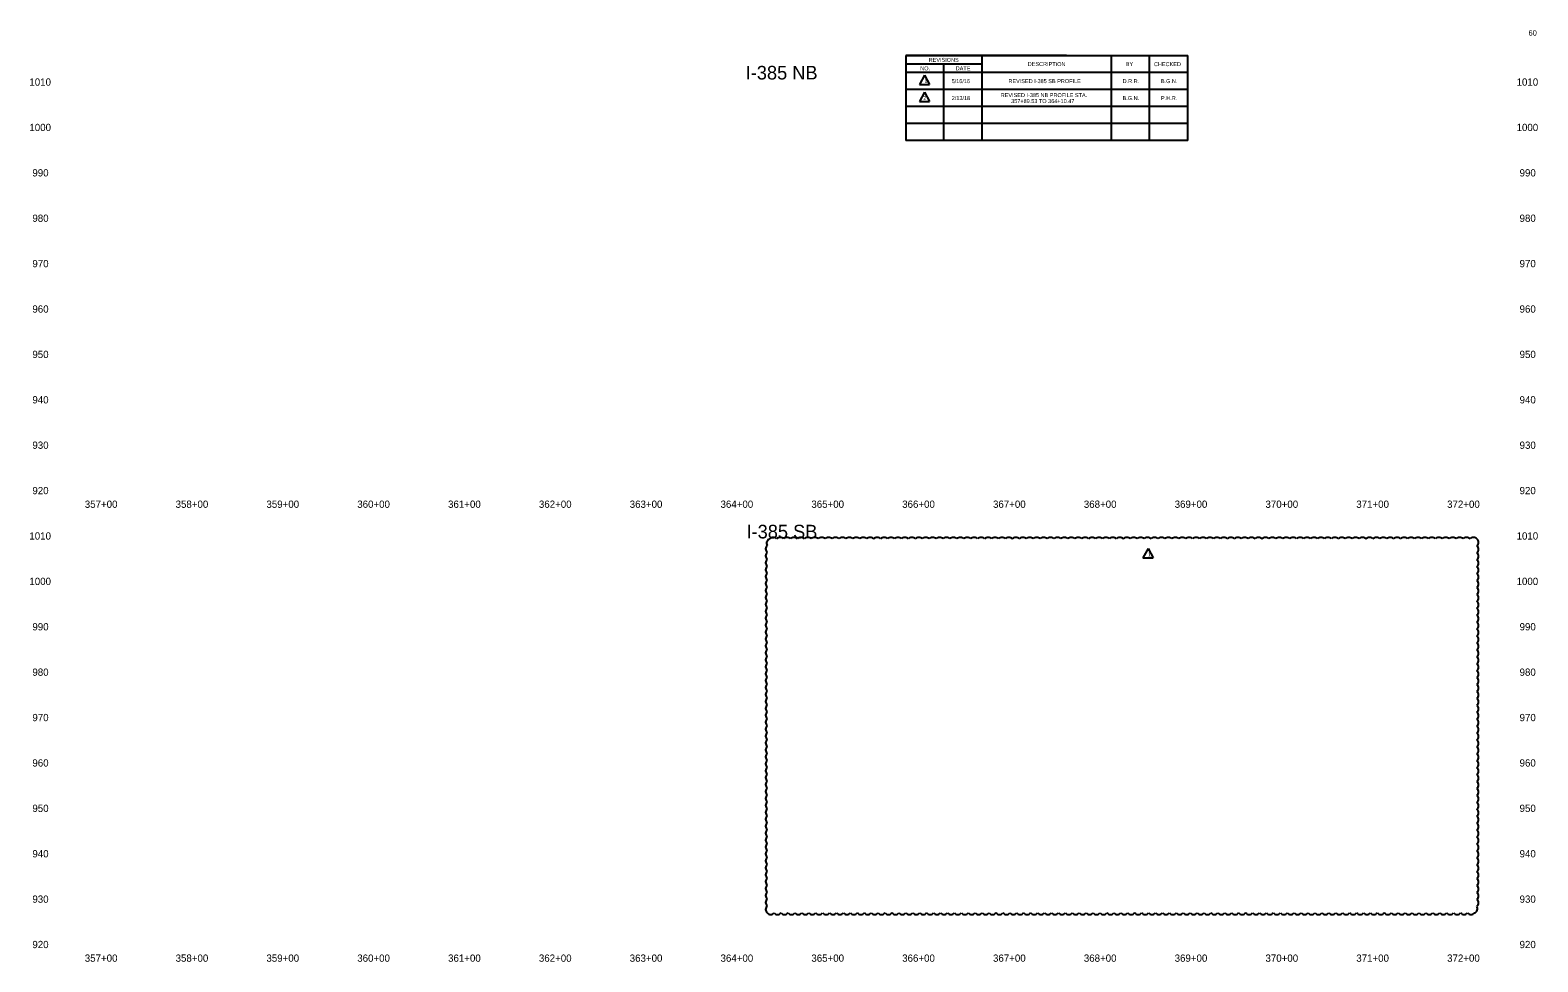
# Model space of a CAD drawing. Extents: x 1616157 to 1617818, y 1076017 to 1077043.
import ezdxf

# ---------------------------------------------------------------- set-up
doc = ezdxf.new("R2010")
doc.units = 0
doc.layers.add('Default', color=7, linetype='Continuous')
doc.layers.add('RD_SHT_TX', color=7, linetype='Continuous')

msp = doc.modelspace()

# ---------------------------------------------------------------- linework, layer by layer
at = {"layer": 'RD_SHT_TX'}
for p, q in [((1617121.5, 1077015.4), (1617432.1, 1077015.4)), ((1617298.7, 1077015.4), (1617121.5, 1077015.4)), ((1617121.5, 1077015.4), (1617121.5, 1076921.9)), ((1617205.5, 1077006.1), (1617121.5, 1077006.1)), ((1617163.5, 1076921.9), (1617163.5, 1077006.1)), ((1617205.5, 1076921.9), (1617205.5, 1077015.4)), ((1617348.1, 1076921.9), (1617348.1, 1077015.4)), ((1617390.1, 1076921.9), (1617390.1, 1077015.4)), ((1617432.1, 1076921.9), (1617432.1, 1077015.4)), ((1617432.1, 1076996.7), (1617121.5, 1076996.7)), ((1617142.1, 1076993.8), (1617136.5, 1076983.6)), ((1617142.1, 1076993.8), (1617147.8, 1076983.6)), ((1617432.1, 1076978), (1617121.5, 1076978)), ((1617136.5, 1076983.6), (1617147.8, 1076983.6)), ((1617142.1, 1076975.1), (1617136.5, 1076964.9)), ((1617142.1, 1076975.1), (1617147.8, 1076964.9)), ((1617432.1, 1076959.3), (1617121.5, 1076959.3)), ((1617136.5, 1076964.9), (1617147.8, 1076964.9)), ((1617432.1, 1076940.6), (1617121.5, 1076940.6)), ((1617432.1, 1076921.9), (1617121.5, 1076921.9)), ((1617388.3, 1076472.4), (1617382.6, 1076462.3)), ((1617388.3, 1076472.4), (1617394, 1076462.3)), ((1617382.6, 1076462.3), (1617394, 1076462.3))]:
    msp.add_line(p, q, dxfattribs=at)
for centre, start, end in [((1616972.2, 1076472.1), 130, 230), ((1616973.3, 1076478.3), 108.9596, 208.9596), ((1616975.5, 1076479.8), 40, 140), ((1616983.2, 1076479.8), 40, 140), ((1616990.8, 1076479.8), 40, 140), ((1616998.4, 1076479.8), 40, 140), ((1617006.1, 1076479.8), 40, 140), ((1617013.7, 1076479.8), 40, 140), ((1617021.3, 1076479.8), 40, 140), ((1617029, 1076479.8), 40, 140), ((1617036.6, 1076479.8), 40, 140), ((1617044.2, 1076479.8), 40, 140), ((1617051.9, 1076479.8), 40, 140), ((1617059.5, 1076479.8), 40, 140), ((1617067.1, 1076479.8), 40, 140), ((1617074.8, 1076479.8), 40, 140), ((1617082.4, 1076479.8), 40, 140), ((1617090, 1076479.8), 40, 140), ((1617097.7, 1076479.8), 40, 140), ((1617105.3, 1076479.8), 40, 140), ((1617113, 1076479.8), 40, 140), ((1617120.6, 1076479.8), 40, 140), ((1617128.2, 1076479.8), 40, 140), ((1617135.9, 1076479.8), 40, 140), ((1617143.5, 1076479.8), 40, 140), ((1617151.1, 1076479.8), 40, 140), ((1617158.8, 1076479.8), 40, 140), ((1617166.4, 1076479.8), 40, 140), ((1617174, 1076479.8), 40, 140), ((1617181.7, 1076479.8), 40, 140), ((1617189.3, 1076479.8), 40, 140), ((1617196.9, 1076479.8), 40, 140), ((1617204.6, 1076479.8), 40, 140), ((1617212.2, 1076479.8), 40, 140), ((1617219.8, 1076479.8), 40, 140), ((1617227.5, 1076479.8), 40, 140), ((1617235.1, 1076479.8), 40, 140), ((1617242.7, 1076479.8), 40, 140), ((1617250.4, 1076479.8), 40, 140), ((1617258, 1076479.8), 40, 140), ((1617265.7, 1076479.8), 40, 140), ((1617273.3, 1076479.8), 40, 140), ((1617280.9, 1076479.8), 40, 140), ((1617288.6, 1076479.8), 40, 140), ((1617296.2, 1076479.8), 40, 140), ((1617303.8, 1076479.8), 40, 140), ((1617311.5, 1076479.8), 40, 140), ((1617319.1, 1076479.8), 40, 140), ((1617326.7, 1076479.8), 40, 140), ((1617334.4, 1076479.8), 40, 140), ((1617342, 1076479.8), 40, 140), ((1617349.6, 1076479.8), 40, 140), ((1617357.3, 1076479.8), 40, 140), ((1617364.9, 1076479.8), 40, 140), ((1617372.5, 1076479.8), 40, 140), ((1617380.2, 1076479.8), 40, 140), ((1617387.8, 1076479.8), 40, 140), ((1617395.4, 1076479.8), 40, 140), ((1617403.1, 1076479.8), 40, 140), ((1617410.7, 1076479.8), 40, 140), ((1617418.4, 1076479.8), 40, 140), ((1617426, 1076479.8), 40, 140), ((1617433.6, 1076479.8), 40, 140), ((1617441.3, 1076479.8), 40, 140), ((1617448.9, 1076479.8), 40, 140), ((1617456.5, 1076479.8), 40, 140), ((1617464.2, 1076479.8), 40, 140), ((1617471.8, 1076479.8), 40, 140), ((1617479.4, 1076479.8), 40, 140), ((1617487.1, 1076479.8), 40, 140), ((1617494.7, 1076479.8), 40, 140), ((1617502.3, 1076479.8), 40, 140), ((1617510, 1076479.8), 40, 140), ((1617517.6, 1076479.8), 40, 140), ((1617525.2, 1076479.8), 40, 140), ((1617532.9, 1076479.8), 40, 140), ((1617540.5, 1076479.8), 40, 140), ((1617548.1, 1076479.8), 40, 140), ((1617555.8, 1076479.8), 40, 140), ((1617563.4, 1076479.8), 40, 140), ((1617571.1, 1076479.8), 40, 140), ((1617578.7, 1076479.8), 40, 140), ((1617586.3, 1076479.8), 40, 140), ((1617594, 1076479.8), 40, 140), ((1617601.6, 1076479.8), 40, 140), ((1617609.2, 1076479.8), 40, 140), ((1617616.9, 1076479.8), 40, 140), ((1617624.5, 1076479.8), 40, 140), ((1617632.1, 1076479.8), 40, 140), ((1617639.8, 1076479.8), 40, 140), ((1617647.4, 1076479.8), 40, 140), ((1617655, 1076479.8), 40, 140), ((1617662.7, 1076479.8), 40, 140), ((1617670.3, 1076479.8), 40, 140), ((1617677.9, 1076479.8), 40, 140), ((1617685.6, 1076479.8), 40, 140), ((1617693.2, 1076479.8), 40, 140), ((1617700.8, 1076479.8), 40, 140), ((1617708.5, 1076479.8), 40, 140), ((1617716.1, 1076479.8), 40, 140), ((1617723.8, 1076479.8), 40, 140), ((1617731.4, 1076479.8), 40, 140), ((1617739, 1076479.8), 40, 140), ((1617746.7, 1076479.8), 40, 140), ((1617747.3, 1076479.2), 310, 50), ((1617747.3, 1076471.5), 310, 50), ((1616972.2, 1076464.4), 130, 230), ((1616972.2, 1076456.8), 130, 230), ((1617747.3, 1076463.9), 310, 50), ((1617747.3, 1076456.3), 310, 50), ((1616972.2, 1076449.1), 130, 230), ((1616972.2, 1076441.5), 130, 230), ((1616972.2, 1076433.9), 130, 230), ((1617747.3, 1076448.6), 310, 50), ((1617747.3, 1076441), 310, 50), ((1617747.3, 1076433.4), 310, 50), ((1616972.2, 1076426.2), 130, 230), ((1616972.2, 1076418.6), 130, 230), ((1617747.3, 1076425.7), 310, 50), ((1617747.3, 1076418.1), 310, 50), ((1616972.2, 1076411), 130, 230), ((1616972.2, 1076403.3), 130, 230), ((1617747.3, 1076410.5), 310, 50), ((1617747.3, 1076402.8), 310, 50), ((1616972.2, 1076395.7), 130, 230), ((1616972.2, 1076388.1), 130, 230), ((1617747.3, 1076395.2), 310, 50), ((1617747.3, 1076387.6), 310, 50), ((1616972.2, 1076380.4), 130, 230), ((1616972.2, 1076372.8), 130, 230), ((1617747.3, 1076379.9), 310, 50), ((1617747.3, 1076372.3), 310, 50), ((1616972.2, 1076365.2), 130, 230), ((1616972.2, 1076357.5), 130, 230), ((1617747.3, 1076364.7), 310, 50), ((1617747.3, 1076357), 310, 50), ((1616972.2, 1076349.9), 130, 230), ((1616972.2, 1076342.3), 130, 230), ((1616972.2, 1076334.6), 130, 230), ((1617747.3, 1076349.4), 310, 50), ((1617747.3, 1076341.7), 310, 50), ((1617747.3, 1076334.1), 310, 50), ((1616972.2, 1076327), 130, 230), ((1616972.2, 1076319.4), 130, 230), ((1617747.3, 1076326.5), 310, 50), ((1617747.3, 1076318.8), 310, 50), ((1616972.2, 1076311.7), 130, 230), ((1616972.2, 1076304.1), 130, 230), ((1617747.3, 1076311.2), 310, 50), ((1617747.3, 1076303.6), 310, 50), ((1616972.2, 1076296.4), 130, 230), ((1616972.2, 1076288.8), 130, 230), ((1617747.3, 1076295.9), 310, 50), ((1617747.3, 1076288.3), 310, 50), ((1616972.2, 1076281.2), 130, 230), ((1616972.2, 1076273.5), 130, 230), ((1617747.3, 1076280.7), 310, 50), ((1617747.3, 1076273), 310, 50), ((1616972.2, 1076265.9), 130, 230), ((1616972.2, 1076258.3), 130, 230), ((1616972.2, 1076250.6), 130, 230), ((1617747.3, 1076265.4), 310, 50), ((1617747.3, 1076257.8), 310, 50), ((1616972.2, 1076243), 130, 230), ((1616972.2, 1076235.4), 130, 230), ((1617747.3, 1076250.1), 310, 50), ((1617747.3, 1076242.5), 310, 50), ((1617747.3, 1076234.9), 310, 50), ((1616972.2, 1076227.7), 130, 230), ((1616972.2, 1076220.1), 130, 230), ((1617747.3, 1076227.2), 310, 50), ((1617747.3, 1076219.6), 310, 50), ((1616972.2, 1076212.5), 130, 230), ((1616972.2, 1076204.8), 130, 230), ((1617747.3, 1076212), 310, 50), ((1617747.3, 1076204.3), 310, 50), ((1616972.2, 1076197.2), 130, 230), ((1616972.2, 1076189.6), 130, 230), ((1617747.3, 1076196.7), 310, 50), ((1617747.3, 1076189), 310, 50), ((1616972.2, 1076181.9), 130, 230), ((1616972.2, 1076174.3), 130, 230), ((1617747.3, 1076181.4), 310, 50), ((1617747.3, 1076173.8), 310, 50), ((1616972.2, 1076166.7), 130, 230), ((1616972.2, 1076159), 130, 230), ((1616972.2, 1076151.4), 130, 230), ((1617747.3, 1076166.1), 310, 50), ((1617747.3, 1076158.5), 310, 50), ((1617747.3, 1076150.9), 310, 50), ((1616972.2, 1076143.7), 130, 230), ((1616972.2, 1076136.1), 130, 230), ((1617747.3, 1076143.2), 310, 50), ((1617747.3, 1076135.6), 310, 50), ((1616972.2, 1076128.5), 130, 230), ((1616972.2, 1076120.8), 130, 230), ((1617747.3, 1076128), 310, 50), ((1617747.3, 1076120.3), 310, 50), ((1616972.2, 1076113.2), 130, 230), ((1616972.2, 1076105.6), 130, 230), ((1617747.3, 1076112.7), 310, 50), ((1617747.3, 1076105.1), 310, 50), ((1616972.2, 1076097.9), 130, 230), ((1616972.2, 1076090.3), 130, 230), ((1617747.3, 1076097.4), 310, 50), ((1617747.3, 1076089.8), 310, 50), ((1616972.2, 1076082.7), 130, 230), ((1616972.2, 1076075), 130, 230), ((1617746.1, 1076075.9), 288.9596, 28.9596), ((1617747.3, 1076082.2), 310, 50), ((1616972.8, 1076074.4), 220, 320), ((1616980.4, 1076074.4), 220, 320), ((1616988.1, 1076074.4), 220, 320), ((1616995.7, 1076074.4), 220, 320), ((1617003.3, 1076074.4), 220, 320), ((1617011, 1076074.4), 220, 320), ((1617018.6, 1076074.4), 220, 320), ((1617026.2, 1076074.4), 220, 320), ((1617033.9, 1076074.4), 220, 320), ((1617041.5, 1076074.4), 220, 320), ((1617049.1, 1076074.4), 220, 320), ((1617056.8, 1076074.4), 220, 320), ((1617064.4, 1076074.4), 220, 320), ((1617072, 1076074.4), 220, 320), ((1617079.7, 1076074.4), 220, 320), ((1617087.3, 1076074.4), 220, 320), ((1617094.9, 1076074.4), 220, 320), ((1617102.6, 1076074.4), 220, 320), ((1617110.2, 1076074.4), 220, 320), ((1617117.8, 1076074.4), 220, 320), ((1617125.5, 1076074.4), 220, 320), ((1617133.1, 1076074.4), 220, 320), ((1617140.8, 1076074.4), 220, 320), ((1617148.4, 1076074.4), 220, 320), ((1617156, 1076074.4), 220, 320), ((1617163.7, 1076074.4), 220, 320), ((1617171.3, 1076074.4), 220, 320), ((1617178.9, 1076074.4), 220, 320), ((1617186.6, 1076074.4), 220, 320), ((1617194.2, 1076074.4), 220, 320), ((1617201.8, 1076074.4), 220, 320), ((1617209.5, 1076074.4), 220, 320), ((1617217.1, 1076074.4), 220, 320), ((1617224.7, 1076074.4), 220, 320), ((1617232.4, 1076074.4), 220, 320), ((1617240, 1076074.4), 220, 320), ((1617247.6, 1076074.4), 220, 320), ((1617255.3, 1076074.4), 220, 320), ((1617262.9, 1076074.4), 220, 320), ((1617270.5, 1076074.4), 220, 320), ((1617278.2, 1076074.4), 220, 320), ((1617285.8, 1076074.4), 220, 320), ((1617293.5, 1076074.4), 220, 320), ((1617301.1, 1076074.4), 220, 320), ((1617308.7, 1076074.4), 220, 320), ((1617316.4, 1076074.4), 220, 320), ((1617324, 1076074.4), 220, 320), ((1617331.6, 1076074.4), 220, 320), ((1617339.3, 1076074.4), 220, 320), ((1617346.9, 1076074.4), 220, 320), ((1617354.5, 1076074.4), 220, 320), ((1617362.2, 1076074.4), 220, 320), ((1617369.8, 1076074.4), 220, 320), ((1617377.4, 1076074.4), 220, 320), ((1617385.1, 1076074.4), 220, 320), ((1617392.7, 1076074.4), 220, 320), ((1617400.3, 1076074.4), 220, 320), ((1617408, 1076074.4), 220, 320), ((1617415.6, 1076074.4), 220, 320), ((1617423.2, 1076074.4), 220, 320), ((1617430.9, 1076074.4), 220, 320), ((1617438.5, 1076074.4), 220, 320), ((1617446.2, 1076074.4), 220, 320), ((1617453.8, 1076074.4), 220, 320), ((1617461.4, 1076074.4), 220, 320), ((1617469.1, 1076074.4), 220, 320), ((1617476.7, 1076074.4), 220, 320), ((1617484.3, 1076074.4), 220, 320), ((1617492, 1076074.4), 220, 320), ((1617499.6, 1076074.4), 220, 320), ((1617507.2, 1076074.4), 220, 320), ((1617514.9, 1076074.4), 220, 320), ((1617522.5, 1076074.4), 220, 320), ((1617530.1, 1076074.4), 220, 320), ((1617537.8, 1076074.4), 220, 320), ((1617545.4, 1076074.4), 220, 320), ((1617553, 1076074.4), 220, 320), ((1617560.7, 1076074.4), 220, 320), ((1617568.3, 1076074.4), 220, 320), ((1617576, 1076074.4), 220, 320), ((1617583.6, 1076074.4), 220, 320), ((1617591.2, 1076074.4), 220, 320), ((1617598.9, 1076074.4), 220, 320), ((1617606.5, 1076074.4), 220, 320), ((1617614.1, 1076074.4), 220, 320), ((1617621.8, 1076074.4), 220, 320), ((1617629.4, 1076074.4), 220, 320), ((1617637, 1076074.4), 220, 320), ((1617644.7, 1076074.4), 220, 320), ((1617652.3, 1076074.4), 220, 320), ((1617659.9, 1076074.4), 220, 320), ((1617667.6, 1076074.4), 220, 320), ((1617675.2, 1076074.4), 220, 320), ((1617682.8, 1076074.4), 220, 320), ((1617690.5, 1076074.4), 220, 320), ((1617698.1, 1076074.4), 220, 320), ((1617705.7, 1076074.4), 220, 320), ((1617713.4, 1076074.4), 220, 320), ((1617721, 1076074.4), 220, 320), ((1617728.7, 1076074.4), 220, 320), ((1617736.3, 1076074.4), 220, 320), ((1617743.9, 1076074.4), 220, 320)]:
    msp.add_arc(centre, 4.98, start, end, dxfattribs=at)

# ---------------------------------------------------------------- texts
at = {"layer": 'Default'}
for s, p in [('1010', (1616156.6, 1076982.3)), ('1010', (1617794.1, 1076982.3)), ('1000', (1616156.6, 1076932.3)), ('1000', (1617794.1, 1076932.3)), ('990', (1616159.9, 1076882.3)), ('990', (1617797.4, 1076882.3)), ('980', (1616159.9, 1076832.3)), ('980', (1617797.4, 1076832.3)), ('970', (1616159.9, 1076782.3)), ('970', (1617797.4, 1076782.3)), ('960', (1616159.9, 1076732.3)), ('960', (1617797.4, 1076732.3)), ('950', (1616159.9, 1076682.3)), ('950', (1617797.4, 1076682.3)), ('940', (1616159.9, 1076632.3)), ('940', (1617797.4, 1076632.3)), ('930', (1616159.9, 1076582.3)), ('930', (1617797.4, 1076582.3)), ('920', (1616159.9, 1076532.3)), ('920', (1617797.4, 1076532.3)), ('357+00', (1616217.6, 1076517.3)), ('358+00', (1616317.6, 1076517.3)), ('359+00', (1616417.6, 1076517.3)), ('360+00', (1616517.6, 1076517.3)), ('361+00', (1616617.6, 1076517.3)), ('362+00', (1616717.6, 1076517.3)), ('363+00', (1616817.6, 1076517.3)), ('364+00', (1616917.6, 1076517.3)), ('365+00', (1617017.6, 1076517.3)), ('366+00', (1617117.6, 1076517.3)), ('367+00', (1617217.6, 1076517.3)), ('368+00', (1617317.6, 1076517.3)), ('369+00', (1617417.6, 1076517.3)), ('370+00', (1617517.6, 1076517.3)), ('371+00', (1617617.6, 1076517.3)), ('372+00', (1617717.6, 1076517.3)), ('1010', (1616156.6, 1076482.3)), ('1010', (1617794.1, 1076482.3)), ('1000', (1616156.6, 1076432.3)), ('1000', (1617794.1, 1076432.3)), ('990', (1616159.9, 1076382.3)), ('990', (1617797.4, 1076382.3)), ('980', (1616159.9, 1076332.3)), ('980', (1617797.4, 1076332.3)), ('970', (1616159.9, 1076282.3)), ('970', (1617797.4, 1076282.3)), ('960', (1616159.9, 1076232.3)), ('960', (1617797.4, 1076232.3)), ('950', (1616159.9, 1076182.3)), ('950', (1617797.4, 1076182.3)), ('940', (1616159.9, 1076132.3)), ('940', (1617797.4, 1076132.3)), ('930', (1616159.9, 1076082.3)), ('930', (1617797.4, 1076082.3)), ('920', (1616159.9, 1076032.3)), ('920', (1617797.4, 1076032.3)), ('357+00', (1616217.6, 1076017.3)), ('358+00', (1616317.6, 1076017.3)), ('359+00', (1616417.6, 1076017.3)), ('360+00', (1616517.6, 1076017.3)), ('361+00', (1616617.6, 1076017.3)), ('362+00', (1616717.6, 1076017.3)), ('363+00', (1616817.6, 1076017.3)), ('364+00', (1616917.6, 1076017.3)), ('365+00', (1617017.6, 1076017.3)), ('366+00', (1617117.6, 1076017.3)), ('367+00', (1617217.6, 1076017.3)), ('368+00', (1617317.6, 1076017.3)), ('369+00', (1617417.6, 1076017.3)), ('370+00', (1617517.6, 1076017.3)), ('371+00', (1617617.6, 1076017.3)), ('372+00', (1617717.6, 1076017.3))]:
    msp.add_text(s, height=8, dxfattribs=at).set_placement(p)
at = {"layer": 'RD_SHT_TX'}
for s, height, p in [('60', 6, (1617807.2, 1077037.4)), ('I-385 NB', 15, (1616945.3, 1076989.1)), ('NO.', 4.4, (1617137.5, 1076999.2)), ('REVISIONS', 4.4, (1617146.8, 1077008.5)), ('CHECKED', 4.4, (1617394.8, 1077003.8)), ('1', 4.4, (1617142.1, 1076985.2)), ('5/16/16', 4.4, (1617172, 1076985.1)), ('REVISED I-385 SB PROFILE', 4.4, (1617234.6, 1076985.1)), ('D.R.R.', 4.4, (1617360.3, 1076985.1)), ('B.G.N.', 4.4, (1617402.5, 1076985.1)), ('2', 4.4, (1617140.9, 1076966.5)), ('2/13/18', 4.4, (1617172.2, 1076966.4)), ('REVISED I-385 NB PROFILE STA. ', 4.4, (1617226.1, 1076969.7)), ('B.G.N.', 4.4, (1617360.3, 1076966.4)), ('P.H.R.', 4.4, (1617402.6, 1076966.4)), ('357+89.53 TO 364+10.47', 4.4, (1617237.6, 1076963.1)), ('I-385 SB', 15, (1616946.2, 1076483.6)), ('1', 4.4, (1617388.3, 1076463.9))]:
    msp.add_text(s, height=height, dxfattribs=at).set_placement(p)
for s, height, p in [('DATE', 4.41, (1617176.5, 1076999.2)), ('DESCRIPTION', 4.408, (1617255.8, 1077004)), ('BY', 4.41, (1617363.8, 1077003.9))]:
    msp.add_text(s, height=height, rotation=359.7246, dxfattribs=at).set_placement(p)

doc.saveas('drawing.dxf')
